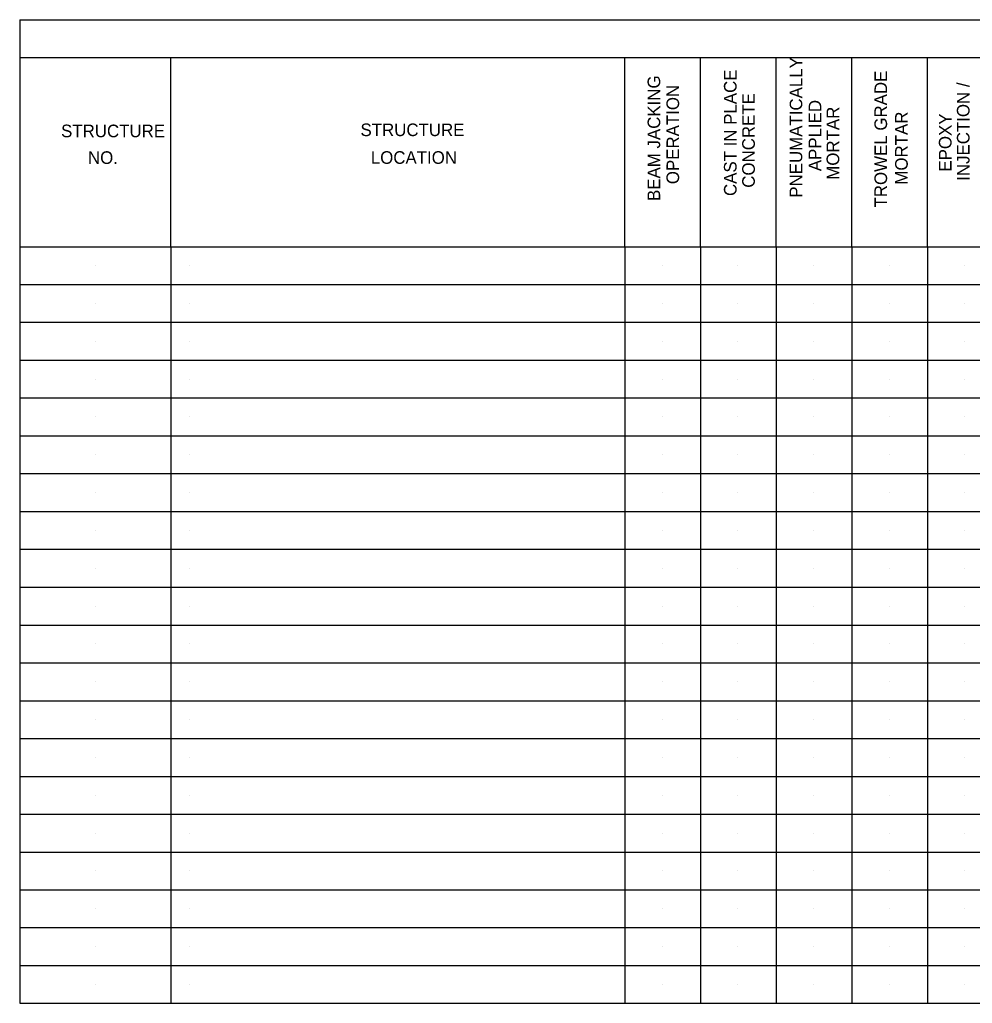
# Model space of a CAD drawing. Extents: x 3.4 to 29.9, y 7.8 to 20.1.
# Drawn here: x 3.42 to 15.32, y 7.79 to 20.08 of the extents above; entities that cross this region are included whole.
import ezdxf

# ---------------------------------------------------------------- set-up
doc = ezdxf.new("R2010")
doc.units = 0
doc.layers.add('ANNO-NOTE', color=7, linetype='Continuous')

msp = doc.modelspace()

# ---------------------------------------------------------------- linework, layer by layer
at = {"layer": 'ANNO-NOTE'}
for p, q in [((3.421, 20.077), (3.421, 7.794)), ((3.421, 20.077), (29.877, 20.077)), ((3.421, 19.605), (29.877, 19.605)), ((5.31, 17.242), (5.31, 19.605)), ((10.98, 17.242), (10.98, 19.605)), ((11.925, 17.242), (11.925, 19.605)), ((12.87, 17.242), (12.87, 19.605)), ((13.814, 17.242), (13.814, 19.605)), ((14.759, 17.242), (14.759, 19.605)), ((3.421, 17.242), (29.877, 17.242)), ((5.31, 17.242), (5.31, 7.794)), ((10.98, 17.242), (10.98, 7.794)), ((11.925, 17.242), (11.925, 7.794)), ((12.87, 17.242), (12.87, 7.794)), ((13.814, 17.242), (13.814, 7.794)), ((14.759, 17.242), (14.759, 7.794)), ((4.362, 17.006), (4.362, 17.006)), ((4.362, 17.006), (4.362, 17.006)), ((5.543, 17.006), (5.543, 17.006)), ((5.543, 17.006), (5.543, 17.006)), ((11.448, 17.006), (11.448, 17.006)), ((11.448, 17.006), (11.448, 17.006)), ((12.393, 17.006), (12.393, 17.006)), ((12.393, 17.006), (12.393, 17.006)), ((13.338, 17.006), (13.338, 17.006)), ((13.338, 17.006), (13.338, 17.006)), ((14.283, 17.006), (14.283, 17.006)), ((15.228, 17.006), (15.228, 17.006)), ((3.421, 16.77), (29.877, 16.77)), ((4.362, 16.534), (4.362, 16.534)), ((4.362, 16.534), (4.362, 16.534)), ((4.362, 16.534), (4.362, 16.534)), ((5.543, 16.534), (5.543, 16.534)), ((5.543, 16.534), (5.543, 16.534)), ((5.543, 16.534), (5.543, 16.534)), ((11.448, 16.534), (11.448, 16.534)), ((11.448, 16.534), (11.448, 16.534)), ((11.448, 16.534), (11.448, 16.534)), ((12.393, 16.534), (12.393, 16.534)), ((12.393, 16.534), (12.393, 16.534)), ((12.393, 16.534), (12.393, 16.534)), ((13.338, 16.534), (13.338, 16.534)), ((13.338, 16.534), (13.338, 16.534)), ((13.338, 16.534), (13.338, 16.534)), ((14.283, 16.534), (14.283, 16.534)), ((14.283, 16.534), (14.283, 16.534)), ((14.283, 16.534), (14.283, 16.534)), ((15.228, 16.534), (15.228, 16.534)), ((15.228, 16.534), (15.228, 16.534)), ((15.228, 16.534), (15.228, 16.534)), ((3.421, 16.298), (29.877, 16.298)), ((4.362, 16.061), (4.362, 16.061)), ((5.543, 16.061), (5.543, 16.061)), ((11.448, 16.061), (11.448, 16.061)), ((12.393, 16.061), (12.393, 16.061)), ((13.338, 16.061), (13.338, 16.061)), ((14.283, 16.061), (14.283, 16.061)), ((15.228, 16.061), (15.228, 16.061)), ((3.421, 15.825), (29.877, 15.825)), ((4.362, 15.589), (4.362, 15.589)), ((5.543, 15.589), (5.543, 15.589)), ((11.448, 15.589), (11.448, 15.589)), ((12.393, 15.589), (12.393, 15.589)), ((13.338, 15.589), (13.338, 15.589)), ((14.283, 15.589), (14.283, 15.589)), ((15.228, 15.589), (15.228, 15.589)), ((3.421, 15.353), (29.877, 15.353)), ((4.362, 15.116), (4.362, 15.116)), ((5.543, 15.116), (5.543, 15.116)), ((11.448, 15.116), (11.448, 15.116)), ((12.393, 15.116), (12.393, 15.116)), ((13.338, 15.116), (13.338, 15.116)), ((14.283, 15.116), (14.283, 15.116)), ((15.228, 15.116), (15.228, 15.116)), ((3.421, 14.88), (29.877, 14.88)), ((4.362, 14.644), (4.362, 14.644)), ((5.543, 14.644), (5.543, 14.644)), ((11.448, 14.644), (11.448, 14.644)), ((12.393, 14.644), (12.393, 14.644)), ((13.338, 14.644), (13.338, 14.644)), ((14.283, 14.644), (14.283, 14.644)), ((15.228, 14.644), (15.228, 14.644)), ((3.421, 14.408), (29.877, 14.408)), ((4.362, 14.172), (4.362, 14.172)), ((5.543, 14.172), (5.543, 14.172)), ((11.448, 14.172), (11.448, 14.172)), ((12.393, 14.172), (12.393, 14.172)), ((13.338, 14.172), (13.338, 14.172)), ((14.283, 14.172), (14.283, 14.172)), ((15.228, 14.172), (15.228, 14.172)), ((3.421, 13.935), (29.877, 13.935)), ((4.362, 13.699), (4.362, 13.699)), ((5.543, 13.699), (5.543, 13.699)), ((11.448, 13.699), (11.448, 13.699)), ((12.393, 13.699), (12.393, 13.699)), ((13.338, 13.699), (13.338, 13.699)), ((14.283, 13.699), (14.283, 13.699)), ((15.228, 13.699), (15.228, 13.699)), ((3.421, 13.463), (29.877, 13.463)), ((4.362, 13.227), (4.362, 13.227)), ((5.543, 13.227), (5.543, 13.227)), ((11.448, 13.227), (11.448, 13.227)), ((12.393, 13.227), (12.393, 13.227)), ((13.338, 13.227), (13.338, 13.227)), ((14.283, 13.227), (14.283, 13.227)), ((15.228, 13.227), (15.228, 13.227)), ((3.421, 12.991), (29.877, 12.991)), ((4.362, 12.754), (4.362, 12.754)), ((5.543, 12.754), (5.543, 12.754)), ((11.448, 12.754), (11.448, 12.754)), ((12.393, 12.754), (12.393, 12.754)), ((13.338, 12.754), (13.338, 12.754)), ((14.283, 12.754), (14.283, 12.754)), ((15.228, 12.754), (15.228, 12.754)), ((3.421, 12.518), (29.877, 12.518)), ((4.362, 12.282), (4.362, 12.282)), ((5.543, 12.282), (5.543, 12.282)), ((11.448, 12.282), (11.448, 12.282)), ((12.393, 12.282), (12.393, 12.282)), ((13.338, 12.282), (13.338, 12.282)), ((14.283, 12.282), (14.283, 12.282)), ((15.228, 12.282), (15.228, 12.282)), ((3.421, 12.046), (29.877, 12.046)), ((4.362, 11.809), (4.362, 11.809)), ((5.543, 11.809), (5.543, 11.809)), ((11.448, 11.809), (11.448, 11.809)), ((12.393, 11.809), (12.393, 11.809)), ((13.338, 11.809), (13.338, 11.809)), ((14.283, 11.809), (14.283, 11.809)), ((15.228, 11.809), (15.228, 11.809)), ((3.421, 11.573), (29.877, 11.573)), ((4.362, 11.337), (4.362, 11.337)), ((5.543, 11.337), (5.543, 11.337)), ((11.448, 11.337), (11.448, 11.337)), ((12.393, 11.337), (12.393, 11.337)), ((13.338, 11.337), (13.338, 11.337)), ((13.338, 11.337), (13.338, 11.337)), ((14.283, 11.337), (14.283, 11.337)), ((15.228, 11.337), (15.228, 11.337)), ((3.421, 11.101), (29.877, 11.101)), ((4.362, 10.864), (4.362, 10.864)), ((4.362, 10.864), (4.362, 10.864)), ((5.543, 10.864), (5.543, 10.864)), ((5.543, 10.864), (5.543, 10.864)), ((11.448, 10.864), (11.448, 10.864)), ((11.448, 10.864), (11.448, 10.864)), ((12.393, 10.864), (12.393, 10.864)), ((12.393, 10.864), (12.393, 10.864)), ((13.338, 10.864), (13.338, 10.864)), ((13.338, 10.864), (13.338, 10.864)), ((14.283, 10.864), (14.283, 10.864)), ((14.283, 10.864), (14.283, 10.864)), ((15.228, 10.864), (15.228, 10.864)), ((15.228, 10.864), (15.228, 10.864)), ((3.421, 10.628), (29.877, 10.628)), ((4.362, 10.392), (4.362, 10.392)), ((5.543, 10.392), (5.543, 10.392)), ((11.448, 10.392), (11.448, 10.392)), ((12.393, 10.392), (12.393, 10.392)), ((13.338, 10.392), (13.338, 10.392)), ((14.283, 10.392), (14.283, 10.392)), ((15.228, 10.392), (15.228, 10.392)), ((3.421, 10.156), (29.877, 10.156)), ((4.362, 9.92), (4.362, 9.92)), ((5.543, 9.92), (5.543, 9.92)), ((11.448, 9.92), (11.448, 9.92)), ((12.393, 9.92), (12.393, 9.92)), ((13.338, 9.92), (13.338, 9.92)), ((14.283, 9.92), (14.283, 9.92)), ((15.228, 9.92), (15.228, 9.92)), ((3.421, 9.683), (29.877, 9.683)), ((4.362, 9.447), (4.362, 9.447)), ((5.543, 9.447), (5.543, 9.447)), ((11.448, 9.447), (11.448, 9.447)), ((12.393, 9.447), (12.393, 9.447)), ((13.338, 9.447), (13.338, 9.447)), ((14.283, 9.447), (14.283, 9.447)), ((15.228, 9.447), (15.228, 9.447)), ((3.421, 9.211), (29.877, 9.211)), ((4.362, 8.975), (4.362, 8.975)), ((5.543, 8.975), (5.543, 8.975)), ((11.448, 8.975), (11.448, 8.975)), ((12.393, 8.975), (12.393, 8.975)), ((13.338, 8.975), (13.338, 8.975)), ((14.283, 8.975), (14.283, 8.975)), ((15.228, 8.975), (15.228, 8.975)), ((3.421, 8.739), (29.877, 8.739)), ((4.362, 8.502), (4.362, 8.502)), ((5.543, 8.502), (5.543, 8.502)), ((11.448, 8.502), (11.448, 8.502)), ((12.393, 8.502), (12.393, 8.502)), ((13.338, 8.502), (13.338, 8.502)), ((14.283, 8.502), (14.283, 8.502)), ((15.228, 8.502), (15.228, 8.502)), ((3.421, 8.266), (29.877, 8.266)), ((4.362, 8.03), (4.362, 8.03)), ((4.362, 8.03), (4.362, 8.03)), ((5.543, 8.03), (5.543, 8.03)), ((11.448, 8.03), (11.448, 8.03)), ((12.393, 8.03), (12.393, 8.03)), ((13.338, 8.03), (13.338, 8.03)), ((14.283, 8.03), (14.283, 8.03)), ((15.228, 8.03), (15.228, 8.03)), ((3.421, 7.794), (29.877, 7.794))]:
    msp.add_line(p, q, dxfattribs=at)

# ---------------------------------------------------------------- texts
for s, height, p in [('PNEUMATICALLY', 0.15748, (13.197, 17.854)), ('CAST IN PLACE', 0.15748, (12.376, 17.875)), ('TROWEL GRADE', 0.15748, (14.256, 17.732)), ('BEAM JACKING', 0.15748, (11.422, 17.813)), ('INJECTION /', 0.15748, (15.286, 18.065)), ('OPERATION', 0.1575, (11.658, 18.023)), ('CONCRETE', 0.1575, (12.604, 17.978)), ('APPLIED', 0.1575, (13.434, 18.185)), ('MORTAR', 0.1575, (13.658, 18.078)), ('MORTAR', 0.1575, (14.514, 18.017)), ('EPOXY', 0.1575, (15.061, 18.18))]:
    msp.add_text(s, height=height, rotation=90, dxfattribs=at).set_placement(p)
for s, p in [('STRUCTURE', (3.938, 18.609)), ('STRUCTURE', (7.678, 18.623)), ('NO.', (4.274, 18.276)), ('LOCATION', (7.807, 18.277))]:
    msp.add_text(s, height=0.1575, dxfattribs=at).set_placement(p)

doc.saveas('drawing.dxf')
